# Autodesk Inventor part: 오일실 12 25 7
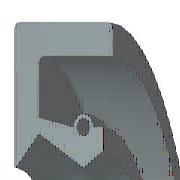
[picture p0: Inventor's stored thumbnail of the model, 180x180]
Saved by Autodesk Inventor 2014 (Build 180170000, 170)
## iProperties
IsCustomPart: 1
Created: 2012-02
Part Number: 오일실 12 25 7
Material: 고무
Description: 오일-실
Document SubType Name: Modeling
Standard: KS B 2804
Designer: test
Standards Organization: KS
Language: ko-KR
Size Designation: D - 12 25 7
Categories: <MemberInstance><Categories><Category DisplayName="샤프트 부품" InternalName="7f7aeb1f-a693-4053-b835-cee3144e0d98" Mnemonic="SHFT"><Category DisplayName="실링" Intern
Density: 0.93 g/cm^3
Appearance: Rubber - Black - Version 1.1
Author: test
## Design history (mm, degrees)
revolve "본체" stored, may be unused: angle "d17" = 90 deg
revolve "스프링1" stored, may be unused: angle "d18" = 90 deg
body "Solid1"
sketch "스케치1"
  geometry: L1 (0, 12.5)-(7, 12.5); L2 (7, 10.75)-(1.75, 10.75); L3 (1.75, 7.75)-(4.9, 6); L4 (4.9, 6)-(0, 6); L5 (0, 0)-(9.586, 0) reference; L6 (4.9, 6)-(6.3, 6.875); L7 (0, 18)-(0, -3) reference; L8 (-1.941, 0)-(11.507, 0) reference; L9 (4.2, 8.1)-(1.75, 8.59); L10 (1.75, 8.59)-(1.75, 10.75); L11 (0, 12.5)-(0, 6.088); L12 (4.9, 6)-(0, 6); L13 (1.75, 7.75)-(0.152, 6.028); L14 (7, 12.5)-(7, 10.75); L15 (5.6, 8.1)-(6.3, 8.1); L16 (6.3, 8.1)-(6.3, 6.875); C1 r 0.455 at (4.9, 8.1); A1 r 0.7 centre (4.9, 8.1) between (5.6, 8.1) and (4.2, 8.1); A2 r 0.088 centre (0.088, 6.088) between (0, 6.088) and (0.152, 6.028); 1 further point
  constraints: 28 end point, 5 horizontal alignment, 5 point on line, 4 point on circle, 4 vertical alignment, 3 centre point, 3 tangent, 2 collinear, 2 horizontal, 2 perpendicular, 1 coincident, 1 parallel
  dimensions: "d0" = 25 diameter of L1 L5 (= SD2); "d1" = 1.75 distance of L1.end L2.start (= SD); "d2" = 0.91 diameter of C1 (= SPDI); "d3" = 1.4 diameter of A1 (= SPDA); "d4" = 12 diameter of L3.end L5 (= NND); "d5" = 15.5 diameter of L3.start L5 (= TKDM); "d7" = 17.18 diameter of L9.end L5 (= TKDM + 0.24 x SWDT); "d8" = 1.75 distance between parallel lines of L11 L10 (= SD); "d9" = 4.9 distance from line of L11 C1.centre (= SPDST); "d10" = 16.2 diameter of C1.centre L5 (= HLDM); "d11" = 0.0875 radius of A2 (= 0.25 x LAB); "d12" = 6.3 distance between parallel lines of L11 L16 (= SDI); "d13" = 13.75 diameter of L6.end L5 (= ABDM); "d14" = 7 distance from line of L11 L1.end (= SWDT)
fillet "모깎기1" dims "d6" = 0.3 (= RR)
other parameters: "SD2" = 25 [user parameter; used in 1 equation term], "SWDT" = 7 [user parameter; used in 2 equation terms], "RR" = 0.3 [user parameter; used in 1 equation term], "SD" = 1.75 [user parameter; used in 2 equation terms], "NND" = 12 [user parameter; used in 1 equation term], "SPDA" = 1.4 [user parameter; used in 1 equation term], "SPDI" = 0.91 [user parameter; used in 1 equation term], "TKDM" = 15.5 [user parameter; used in 2 equation terms], "HLDM" = 16.2 [user parameter; used in 1 equation term], "ABDM" = 13.75 [user parameter; used in 1 equation term], "SDI" = 6.3 [user parameter; used in 1 equation term], "SPDST" = 4.9 [user parameter; used in 1 equation term], "LAB" = 0.35 [user parameter; used in 1 equation term], "d15" = 0, "d16" = 0, "d19" = 0
